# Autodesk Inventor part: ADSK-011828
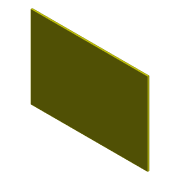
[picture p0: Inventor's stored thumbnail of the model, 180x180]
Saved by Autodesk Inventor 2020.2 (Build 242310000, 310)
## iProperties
Created: 1999-11
Part Number: ADSK-011828
Document SubType Name: Modeling
Designer: sspink
Material: Générique
Density: 1 g/cm^3
Appearance: Gelb
Mass: 107.564 g
Surface Area: 740.16 cm^2
Volume: 107.564 cm^3
Control State: 0
Checked Out: False
Last Check In By: sspink
Last Check In Date: 1999-12-22
Master: False
Shininess: 0.0
Length Units: 11269
Angle Units: 11279
Time Units: 11290
Mass Units: 11283
Length Display Precision: 3
Angle Display Precision: 2
Compacted: True
Dimensions: 159x3x225,5 mm
Mass: 0,108 kg
VLT_Material: Generisch
Density: 0.0
Volumn: 0.0
Area: 0.0
PropertySet Name: Model Information
Author: sspink
Revision Number: -
Title: ADSK-011828
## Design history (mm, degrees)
node "Solide1"
  node "Extrusion1" dims "d1" = 3, "d2" = 0
sketch "Sketch1"
  geometry: L1 (-112.75, 79.5)-(112.75, 79.5); L2 (112.75, 79.5)-(112.75, -79.5); L3 (112.75, -79.5)-(-112.75, -79.5); L4 (-112.75, -79.5)-(-112.75, 79.5); 3 further points
  constraints: 8 end point, 2 midpoint, 2 perpendicular, 1 horizontal alignment, 1 parallel, 1 vertical, 1 vertical alignment
  dimensions: "d4" = 159 distance of L1.end L2.end; "d5" = 225.5 distance of L1.start L1.end
workplane "Work Plane1"
workplane "Work Plane2"
node "Corps solides"
node "Corps surfaciques"
other parameters: "d6" = -79.375, "d7" = -112.7125
